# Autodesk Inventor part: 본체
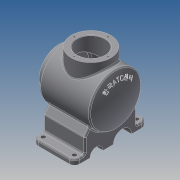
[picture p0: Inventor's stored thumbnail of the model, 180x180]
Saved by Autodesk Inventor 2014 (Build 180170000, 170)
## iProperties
Created: 2018-08
Part Number: 본체
Material: Generic
Document SubType Name: Modeling
Designer: kb542-19
Density: 1 g/cm^3
Appearance: Default
Author: kb542-19
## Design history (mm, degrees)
sketch "스케치1"
  geometry: L1 (-60, 0)-(60, 0); L2 (-60, 38)-(-48, 38); L3 (-48, 38)-(-48, 50); L4 (-48, 50)-(48.671, 50); L5 (-60, 38)-(-60, 27); L6 (-60, 27)-(-38, 27); L7 (-38, 27)-(-38, 40); L8 (-38, 40)-(42.163, 40); A1 r 116 centre (-56, 0) between (60, 0) and (48.671, 50); A2 r 106 centre (-56, 0) between (50, 0) and (42.163, 40); 2 further points
  constraints: 16 end point, 4 parallel, 4 point on circle, 3 perpendicular, 2 centre point, 1 coincident, 1 horizontal, 1 horizontal alignment, 1 midpoint, 1 point on line, 1 vertical alignment
  dimensions: "d0" = 116 radius of A1; "d2" = 100 diameter of L4 L1; "d3" = 12 distance of L2.start L2.end; "d4" = 108 distance from line of L1.end L3; "d5" = 54 diameter of L6 L1; "d6" = 76 diameter of L2 L1; "d7" = 22 distance of L5.end L6.end; "d8" = 10 radial gap between concentric circles of A1 A2; "d9" = 80 diameter of L8 L1
revolve "회전1" sketch "스케치1" stored, may be unused: angle "d10" = 90 deg
node "작업 평면1"
sketch "스케치2"
  geometry: L1 (-48, -50)-(-48, 50) reference; L2 (40, -70)-(-40, -70); L3 (-40, -70)-(-40, 70); L4 (-40, 70)-(40, 70); L5 (40, 70)-(40, -70); L6 (40, -70)-(-40, 70); L7 (-40, -70)-(40, 70); 3 further points
  constraints: 12 end point, 3 midpoint, 2 parallel, 1 coincident, 1 horizontal, 1 perpendicular
  dimensions: "d12" = 140 distance of L4.end L2.start; "d13" = 8 distance between parallel lines of L1 L3; "d14" = 80 distance of L2.start L2.end
extrude "돌출1" join sketch "스케치2" distance "d15" = 10; taper "d16" = 0 deg
fillet "모깎기1" dims "d17" = 10
sketch "스케치3"
  geometry: A1 r 10 centre (30, 60) between (40, 60) and (30, 70) reference; A2 r 10 centre (-30, 60) between (-30, 70) and (-40, 60) reference; A3 r 10 centre (-30, -60) between (-40, -60) and (-30, -70) reference; A4 r 10 centre (30, -60) between (30, -70) and (40, -60) reference; 5 further points
  constraints: 4 coincident
hole "구멍1" sketch "스케치3" at (-30, 60), (30, 60), (30, -60), (-30, -60) diameter "d18" = 8; stored, may be unused: countersink angle "d22" = 90 deg, drill point angle "d24" = 118 deg; dims "d19" = 6, "d20" = 4, "d21" = 2, "d23" = 8
sketch "스케치4"
  geometry: L1 (10, 120)-(10, 0) reference; L2 (0, 0)-(0, 120) reference; L3 (10, 110)-(38.563, 110); L4 (10, 130)-(0, 130) reference; L5 (10, 10)-(38.563, 10); L6 (0, -10)-(10, -10) reference; L7 (38.563, 110)-(52.41, 100.304); L8 (10, 130)-(38.563, 110); L9 (38.563, 10)-(52.41, 19.696); L10 (10, -10)-(38.563, 10); L11 (10, 0)-(10, 120) reference; L12 (10, 10)-(10, 110); C1 r 38 at (82, 60) reference; A1 r 50 centre (82, 60) between (52.41, 100.304) and (52.41, 19.696) reference; 1 further point
  constraints: 14 end point, 3 collinear, 2 point on circle, 2 point on line, 1 parallel, 1 perpendicular
  dimensions: "d25" = 20 distance between parallel lines of L4 L3; "d26" = 20 distance between parallel lines of L6 L5; "d28" = 35 deg angle of L4 L7; "d30" = 0 distance from line of L5.start L1; "d31" = 35 deg angle of L9 L6
extrude "돌출2" join sketch "스케치4" stored distance "d32" = 10; taper "d33" = 0 deg
node "작업 평면2"
sketch "스케치6"
  geometry: L1 (-48, -50)-(-48, 50) reference; C1 r 38 at (2, 0); 1 further point
  constraints: 1 centre point
  dimensions: "d41" = 50 distance from line of L1 C1.centre; "d42" = 76 diameter of C1
extrude "돌출4" join sketch "스케치6" stored distance "d43" = 10; taper "d44" = 0 deg
sketch "스케치7"
  geometry: C1 r 38 at (0, 0) reference; C2 r 27 at (0, 0); 1 further point
  constraints: 1 centre point, 1 concentric
  dimensions: "d45" = 54 diameter of C2
extrude "돌출5" cut sketch "스케치7" stored distance "d46" = 10; taper "d47" = 0 deg
sketch "스케치8" dims "d48" = 65
  geometry: C1 r 27 at (0, 0) reference; C2 r 38 at (0, 0) reference; 3 further points
  constraints: 2 vertical alignment, 3 other
hole "구멍2" sketch "스케치8" at (0, 32.5) diameter "d49" = 3.242; stored, may be unused: countersink angle "d53" = 90 deg, drill point angle "d55" = 118 deg; dims "d50" = 8, "d51" = 4, "d52" = 2, "d54" = 10
sketch "스케치9"
  geometry: C1 r 38 at (0, 0) reference; 1 further point
  constraints: 1 horizontal alignment
  dimensions: "d59" = 32.5 distance of C1.centre point (32.5, 0)
hole "구멍3" sketch "스케치9" at (32.5, 0) diameter "d60" = 3.242; stored, may be unused: countersink angle "d64" = 90 deg, drill point angle "d66" = 118 deg; dims "d61" = 8, "d62" = 4, "d63" = 2, "d65" = 10
node "작업 평면3"
sketch "스케치10"
  geometry: C1 r 32.5 at (0, 0); 1 further point
  constraints: 1 centre point, 1 coincident, 1 other
  dimensions: "d71" = 65 diameter of C1
feature "엠보싱1" sketch "스케치10" dims "d12" = 140, "d13" = 8, "d14" = 80, "d72" = 0.5, "d73" = 0
fillet "모깎기2" dims "d74" = 3
chamfer "모따기1" distance "d75" = 1; stored, may be unused: second distance "d76" = 2, angle "d77" = 45 deg
fillet "모깎기3" dims "d78" = 3
fillet "모깎기4" dims "d79" = 3
fillet "모깎기5" dims "d80" = 3
sketch "스케치12"
  geometry: L1 (0, 120)-(0, 0) reference; C1 r 12.5 at (0, 32.5); C2 r 17.5 at (0, 82.5); A1 r 53 centre (-82, 60) between (-47.401, 19.851) and (-47.401, 100.149) reference
  constraints: 2 centre point, 2 point on line
  dimensions: "d81" = 27.5 vertical distance of A1.centre C1.centre; "d82" = 22.5 vertical distance of A1.centre C2.centre; "d83" = 25 diameter of C1; "d84" = 35 diameter of C2
extrude "돌출6" cut sketch "스케치12" stored distance "d85" = 10; taper "d86" = 0 deg
node "솔리드1"
pattern_circular "원형 패턴1" dims angle "d57" = 360 deg
pattern_circular "원형 패턴2" dims angle "d68" = 360 deg
node "투영된 루프1"
other parameters: "d11" = -82, "d27" = 35 deg, "d40" = -147, "d70" = -108
